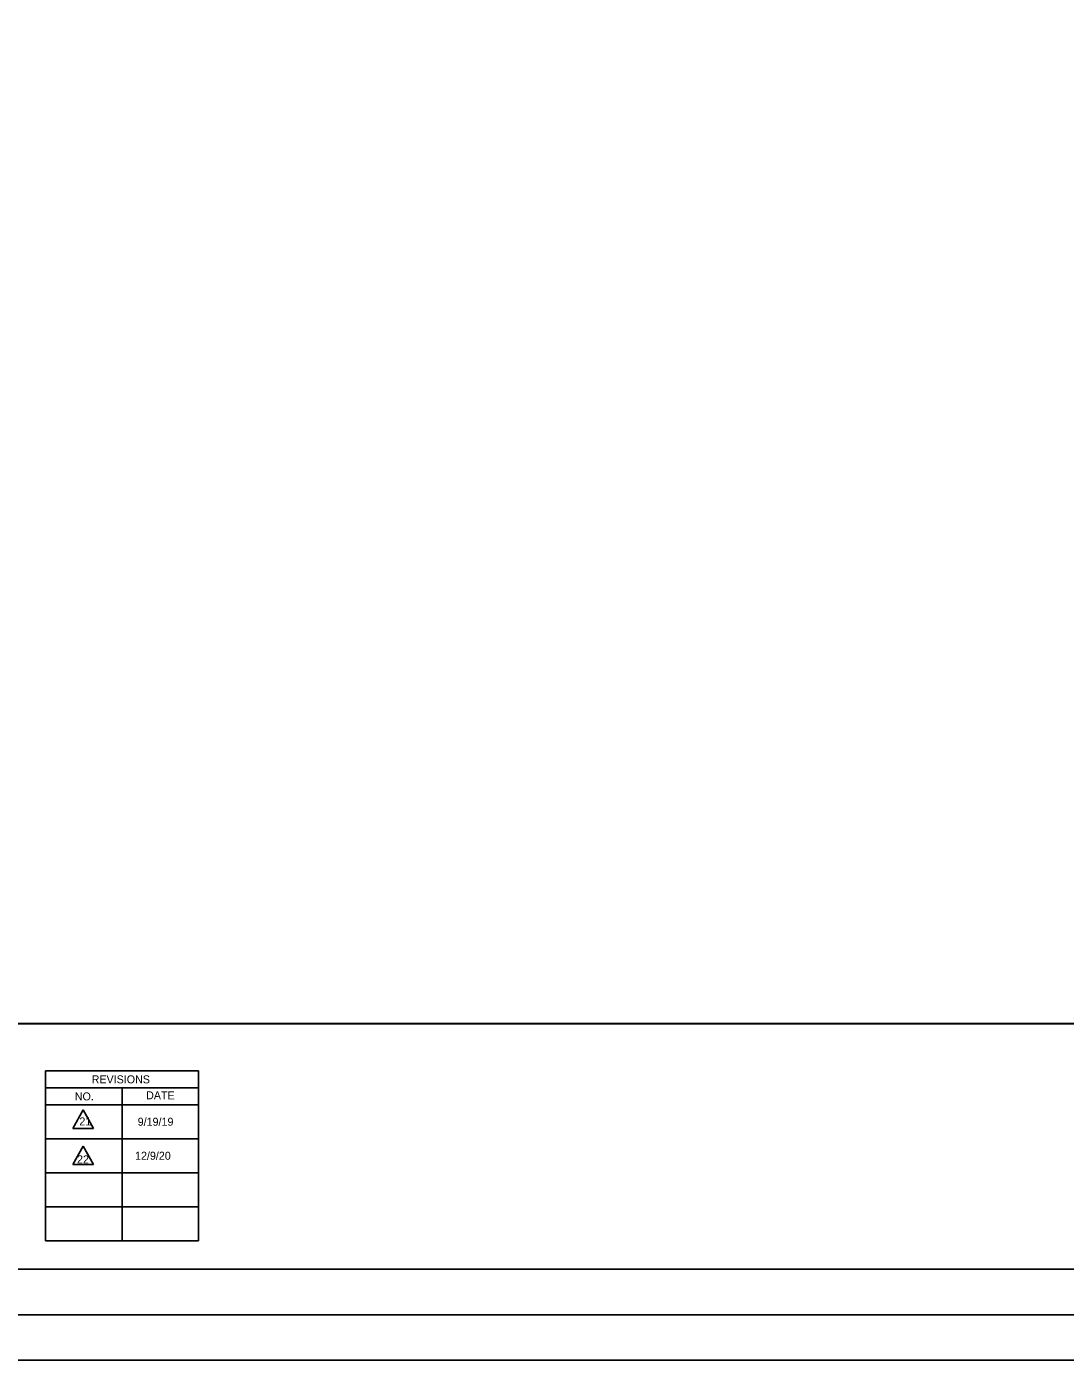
# Model space of a CAD drawing. Extents: x -2251 to 10196, y -13470 to 1199.
# Drawn here: x 5667 to 6237, y -5951 to -5217 of the extents above; entities that cross this region are included whole.
import ezdxf

# ---------------------------------------------------------------- set-up
doc = ezdxf.new("R2010")
doc.units = 0
for name, color, linetype in [('RD_SHT_Bndy', 7, 'Continuous'), ('RD_SHT_Iplotshp', 7, 'Continuous'), ('RD_SHT_Misc1', 7, 'Continuous'), ('RD_SHT_Snap', 7, 'Continuous'), ('RD_SHT_TX', 7, 'Continuous'), ('RD_TX_RoadID', 7, 'Continuous')]:
    doc.layers.add(name, color=color, linetype=linetype)

msp = doc.modelspace()

# ---------------------------------------------------------------- linework, layer by layer
at = {"layer": 'RD_SHT_Bndy'}
for p, q in [((5103.1, -5900.65), (6778.1, -5900.65)), ((6050.94, -5900.65), (5836.06, -5900.65)), ((6791.65, -5925.65), (5031.65, -5925.65)), ((6791.6, -5950.7), (5031.6, -5950.65))]:
    msp.add_line(p, q, dxfattribs=at)
msp.add_lwpolyline([(5153.4, -4901.26), (6731.08, -4901.26), (6731.08, -5765.57), (5153.4, -5765.57)], close=True, dxfattribs=at)
at = {"layer": 'RD_SHT_Iplotshp'}
msp.add_lwpolyline([(4996.65, -4825.65), (6796.65, -4825.65), (6796.65, -5925.65), (4996.65, -5925.65)], close=True, dxfattribs=at)
at = {"layer": 'RD_SHT_Misc1'}
msp.add_lwpolyline([(6796.65, -5925.65), (6796.68, -4825.65), (5096.68, -4825.6), (5096.65, -5925.6)], close=True, dxfattribs=at)
at = {"layer": 'RD_SHT_Snap'}
msp.add_lwpolyline([(5008.15, -4825.65), (6808.15, -4825.65), (6808.15, -5925.65), (5008.15, -5925.65)], close=True, dxfattribs=at)
at = {"layer": 'RD_SHT_TX'}
for p, q in [((5760.93, -5791.56), (5676.93, -5791.56)), ((5676.93, -5791.56), (5676.93, -5885.05)), ((5760.93, -5885.05), (5760.93, -5791.56)), ((5760.93, -5800.91), (5676.93, -5800.91)), ((5718.93, -5885.05), (5718.93, -5800.91)), ((5760.93, -5810.25), (5676.93, -5810.25)), ((5697.48, -5813.04), (5691.79, -5823.18)), ((5697.48, -5813.04), (5703.18, -5823.18)), ((5760.93, -5828.95), (5676.93, -5828.95)), ((5691.79, -5823.18), (5703.18, -5823.18)), ((5697.48, -5832.93), (5691.79, -5843.07)), ((5697.48, -5832.93), (5703.18, -5843.07)), ((5691.79, -5843.07), (5703.18, -5843.07)), ((5760.93, -5847.65), (5676.93, -5847.65)), ((5760.93, -5866.35), (5676.93, -5866.35)), ((5760.93, -5885.05), (5676.93, -5885.05))]:
    msp.add_line(p, q, dxfattribs=at)
at = {"layer": 'RD_TX_RoadID'}
msp.add_lwpolyline([(5150.54, -5765.73), (6733.93, -5765.73), (6733.93, -4962.61), (5150.54, -4962.61)], close=True, dxfattribs=at)

# ---------------------------------------------------------------- texts
at = {"layer": 'RD_SHT_TX'}
for s, height, rotation, p in [('REVISIONS', 4.4, 360, (5702.22, -5798.43)), ('NO.', 4.4, 360, (5692.95, -5807.78)), ('DATE', 4.408, 359.72458, (5732.12, -5807.19))]:
    msp.add_text(s, height=height, rotation=rotation, dxfattribs=at).set_placement(p)
for s, p in [('21', (5695.46, -5821.54)), ('9/19/19', (5727.53, -5821.72)), ('12/9/20', (5726.07, -5840.42)), ('22', (5694.19, -5842.42))]:
    msp.add_text(s, height=4.4, dxfattribs=at).set_placement(p)

doc.saveas('drawing.dxf')
